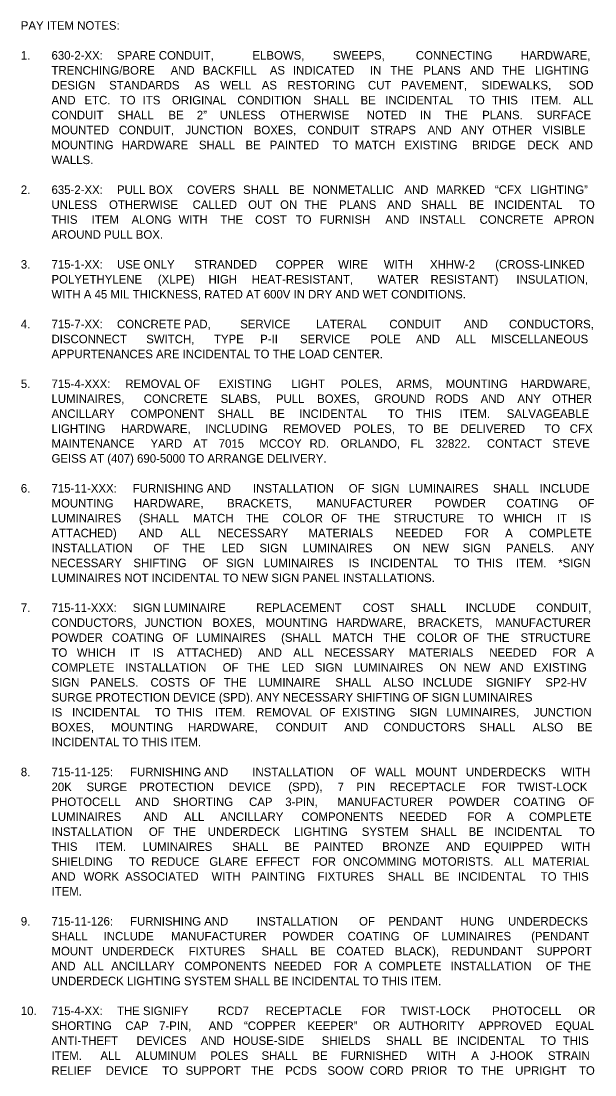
# Model space of a CAD drawing. Extents: x -55 to 2471539, y -90 to 3608906.
# Drawn here: x 27 to 498, y 2532 to 3397 of the extents above; entities that cross this region are included whole.
import ezdxf

# ---------------------------------------------------------------- set-up
doc = ezdxf.new("R2010")
doc.units = 0
doc.layers.add('XSCell', color=7, linetype='Continuous')

msp = doc.modelspace()

# ---------------------------------------------------------------- texts
at = {"layer": 'XSCell'}
for s, p in [('PAY ITEM NOTES:', (26.68, 3389.74)), ('630-2-XX:', (51.88, 3365.24)), (' SPARE CONDUIT, ', (103, 3365.24)), ('ELBOWS, ', (216.8, 3365.24)), ('SWEEPS, ', (282.82, 3365.24)), ('CONNECTING ', (350.92, 3365.24)), ('1.', (26.68, 3365.24)), ('HARDWARE, ', (437.06, 3365.24)), ('TRENCHING/BORE ', (51.88, 3352.99)), ('AND ', (149.66, 3352.99)), ('BACKFILL ', (176.11, 3352.99)), ('AS ', (231.06, 3352.99)), ('INDICATED ', (249.96, 3352.99)), ('IN ', (313.22, 3352.99)), ('THE ', (330.09, 3352.99)), ('PLANS ', (357.07, 3352.99)), ('AND ', (395.32, 3352.99)), ('THE ', (421.77, 3352.99)), ('LIGHTING ', (448.75, 3352.99)), ('DESIGN ', (51.88, 3340.74)), ('STANDARDS ', (99.2, 3340.74)), ('AS ', (169.29, 3340.74)), ('WELL ', (190.33, 3340.74)), ('AS ', (224.46, 3340.74)), ('RESTORING ', (245.49, 3340.74)), ('CUT ', (311.63, 3340.74)), ('PAVEMENT, ', (338.81, 3340.74)), ('SIDEWALKS, ', (404.84, 3340.74)), ('SOD ', (476.42, 3340.74)), ('AND ', (51.88, 3328.49)), ('ETC. ', (78.98, 3328.49)), ('TO ', (107.88, 3328.49)), ('ITS ', (126.69, 3328.49)), ('ORIGINAL ', (150.74, 3328.49)), ('CONDITION ', (204.43, 3328.49)), ('SHALL ', (266.79, 3328.49)), ('BE ', (305.52, 3328.49)), ('INCIDENTAL ', (325.8, 3328.49)), ('TO ', (394.52, 3328.49)), ('THIS ', (413.34, 3328.49)), ('ITEM. ', (445.46, 3328.49)), ('ALL ', (480.05, 3328.49)), ('CONDUIT ', (51.88, 3316.24)), ('SHALL ', (106.12, 3316.24)), ('BE ', (147.86, 3316.24)), ('2” ', (171.15, 3316.24)), ('UNLESS ', (190.04, 3316.24)), ('OTHERWISE ', (239.61, 3316.24)), ('NOTED ', (310.61, 3316.24)), ('IN ', (354.19, 3316.24)), ('THE ', (374.74, 3316.24)), ('PLANS. ', (405.39, 3316.24)), ('SURFACE ', (450.07, 3316.24)), ('MOUNTED ', (51.88, 3303.99)), ('CONDUIT, ', (107.18, 3303.99)), ('JUNCTION ', (161.77, 3303.99)), ('BOXES, ', (217.91, 3303.99)), ('CONDUIT ', (262.01, 3303.99)), ('STRAPS ', (313.55, 3303.99)), ('AND ', (360.6, 3303.99)), ('ANY ', (388, 3303.99)), ('OTHER ', (413.64, 3303.99)), ('VISIBLE ', (454.83, 3303.99)), ('MOUNTING ', (51.88, 3291.74)), ('HARDWARE ', (109.45, 3291.74)), ('SHALL ', (172.87, 3291.74)), ('BE ', (211.11, 3291.74)), ('PAINTED ', (230.91, 3291.74)), ('TO ', (282.44, 3291.74)), ('MATCH ', (300.77, 3291.74)), ('EXISTING ', (341.5, 3291.74)), ('BRIDGE ', (397.1, 3291.74)), ('DECK ', (442.4, 3291.74)), ('AND ', (476.52, 3291.74)), ('WALLS.', (51.88, 3279.49)), ('2.', (26.68, 3254.99)), ('635-2-XX:', (51.88, 3254.99)), (' PULL BOX ', (103, 3254.99)), ('COVERS ', (163.1, 3254.99)), ('SHALL ', (209.1, 3254.99)), ('BE ', (246.91, 3254.99)), ('NONMETALLIC ', (266.27, 3254.99)), ('AND ', (341.51, 3254.99)), ('MARKED ', (367.7, 3254.99)), ('“CFX ', (415.84, 3254.99)), ('LIGHTING” ', (444.82, 3254.99)), ('UNLESS ', (51.88, 3242.74)), ('OTHERWISE ', (99.08, 3242.74)), ('CALLED ', (167.72, 3242.74)), ('OUT ', (213.33, 3242.74)), ('ON ', (239.5, 3242.74)), ('THE ', (259.52, 3242.74)), ('PLANS ', (287.82, 3242.74)), ('AND ', (327.38, 3242.74)), ('SHALL ', (355.13, 3242.74)), ('BE ', (394.51, 3242.74)), ('INCIDENTAL ', (415.44, 3242.74)), ('TO ', (484.81, 3242.74)), ('THIS ', (51.88, 3230.49)), ('ITEM ', (84.87, 3230.49)), ('ALONG ', (117.57, 3230.49)), ('WITH ', (156.2, 3230.49)), ('THE ', (190.47, 3230.49)), ('COST ', (218.99, 3230.49)), ('TO ', (252.31, 3230.49)), ('FURNISH ', (272, 3230.49)), ('AND ', (325.85, 3230.49)), ('INSTALL ', (353.83, 3230.49)), ('CONCRETE ', (403.21, 3230.49)), ('APRON ', (464.1, 3230.49)), ('AROUND PULL BOX.', (51.88, 3218.24)), ('3.', (26.68, 3193.74)), ('715-1-XX:', (51.88, 3193.74)), (' USE ONLY ', (103, 3193.74)), ('STRANDED ', (169.1, 3193.74)), ('COPPER ', (235.88, 3193.74)), ('WIRE ', (287.14, 3193.74)), ('WITH ', (324.62, 3193.74)), ('XHHW-2 ', (362.53, 3193.74)), ('(CROSS-LINKED ', (416.09, 3193.74)), ('POLYETHYLENE ', (51.88, 3181.49)), ('(XLPE) ', (139.17, 3181.49)), ('HIGH ', (180.77, 3181.49)), ('HEAT-RESISTANT, ', (216.17, 3181.49)), ('WATER ', (319.51, 3181.49)), ('RESISTANT) ', (362.99, 3181.49)), ('INSULATION, ', (433.46, 3181.49)), ('WITH A 45 MIL THICKNESS, RATED AT 600V IN DRY AND WET CONDITIONS.', (51.88, 3169.24)), ('4.', (26.68, 3144.74)), ('715-7-XX:', (51.88, 3144.74)), (' CONCRETE PAD, ', (103, 3144.74)), ('SERVICE ', (206.77, 3144.74)), ('LATERAL ', (268.9, 3144.74)), ('CONDUIT ', (329.2, 3144.74)), ('AND ', (390.35, 3144.74)), ('CONDUCTORS, ', (427.37, 3144.74)), ('DISCONNECT ', (51.88, 3132.49)), ('SWITCH, ', (129.64, 3132.49)), ('TYPE ', (185.25, 3132.49)), ('P-II ', (223.15, 3132.49)), ('SERVICE ', (255.82, 3132.49)), ('POLE ', (313.56, 3132.49)), ('AND ', (351.06, 3132.49)), ('ALL ', (383.69, 3132.49)), ('MISCELLANEOUS ', (412.79, 3132.49)), ('APPURTENANCES ARE INCIDENTAL TO THE LOAD CENTER.', (51.88, 3120.24)), ('5.', (26.68, 3095.74)), ('715-4-XXX:', (51.88, 3095.74)), (' REMOVAL OF ', (109.83, 3095.74)), ('EXISTING ', (189.18, 3095.74)), ('LIGHT ', (248.74, 3095.74)), ('POLES, ', (289.22, 3095.74)), ('ARMS, ', (334.82, 3095.74)), ('MOUNTING ', (375.52, 3095.74)), ('HARDWARE, ', (437.06, 3095.74)), ('LUMINAIRES, ', (51.88, 3083.49)), ('CONCRETE ', (127.57, 3083.49)), ('SLABS, ', (190.68, 3083.49)), ('PULL ', (236.09, 3083.49)), ('BOXES, ', (269.91, 3083.49)), ('GROUND ', (316.81, 3083.49)), ('RODS ', (366.94, 3083.49)), ('AND ', (404.11, 3083.49)), ('ANY ', (434.3, 3083.49)), ('OTHER ', (462.73, 3083.49)), ('ANCILLARY ', (51.88, 3071.24)), ('COMPONENT ', (116.74, 3071.24)), ('SHALL ', (188.11, 3071.24)), ('INCIDENTAL ', (255.18, 3071.24)), ('TO ', (327.94, 3071.24)), ('THIS ', (350.78, 3071.24)), ('SALVAGEABLE ', (425.56, 3071.24)), ('BE ', (230.87, 3071.24)), ('ITEM. ', (386.93, 3071.24)), ('LIGHTING ', (51.88, 3058.99)), ('HARDWARE, ', (108.88, 3058.99)), ('INCLUDING ', (177.96, 3058.99)), ('REMOVED ', (242, 3058.99)), ('POLES, ', (299.96, 3058.99)), ('TO ', (344.21, 3058.99)), ('BE ', (365.15, 3058.99)), ('DELIVERED ', (387.56, 3058.99)), ('TO ', (456.32, 3058.99)), ('CFX ', (477.26, 3058.99)), ('MAINTENANCE ', (51.88, 3046.74)), ('YARD ', (133.12, 3046.74)), ('AT ', (168.17, 3046.74)), ('7015 ', (189.1, 3046.74)), ('MCCOY ', (222.38, 3046.74)), ('RD. ', (263.67, 3046.74)), ('ORLANDO, ', (289.13, 3046.74)), ('FL ', (346.54, 3046.74)), ('32822. ', (366.95, 3046.74)), ('CONTACT ', (409.27, 3046.74)), ('STEVE ', (463.01, 3046.74)), ('GEISS AT (407) 690-5000 TO ARRANGE DELIVERY.', (51.88, 3034.49)), ('6.', (26.68, 3009.99)), ('715-11-XXX:', (51.88, 3009.99)), (' FURNISHING AND ', (115.94, 3009.99)), ('INSTALLATION ', (217.19, 3009.99)), ('OF ', (295.86, 3009.99)), ('SIGN ', (314.55, 3009.99)), ('LUMINAIRES ', (345.11, 3009.99)), ('SHALL ', (414.2, 3009.99)), ('INCLUDE ', (452.46, 3009.99)), ('MOUNTING ', (51.88, 2997.74)), ('HARDWARE, ', (119.48, 2997.74)), ('BRACKETS, ', (195.97, 2997.74)), ('MANUFACTURER ', (269.31, 2997.74)), ('POWDER ', (366.37, 2997.74)), ('COATING ', (425.27, 2997.74)), ('OF ', (484.48, 2997.74)), ('LUMINAIRES ', (51.88, 2985.49)), ('(SHALL ', (123.68, 2985.49)), ('MATCH ', (168.01, 2985.49)), ('THE ', (211.48, 2985.49)), ('COLOR ', (241.38, 2985.49)), ('OF ', (281.43, 2985.49)), ('THE ', (302.84, 2985.49)), ('STRUCTURE ', (332.74, 2985.49)), ('TO ', (401.75, 2985.49)), ('WHICH ', (422.82, 2985.49)), ('IT ', (466.72, 2985.49)), ('IS ', (485.95, 2985.49)), ('ATTACHED) ', (51.88, 2973.24)), ('AND ', (123.47, 2973.24)), ('ALL ', (157.72, 2973.24)), ('NECESSARY ', (188.45, 2973.24)), ('MATERIALS ', (262.81, 2973.24)), ('NEEDED ', (334.12, 2973.24)), ('FOR ', (391.05, 2973.24)), ('A ', (424.22, 2973.24)), ('COMPLETE ', (443.85, 2973.24)), ('INSTALLATION ', (51.88, 2960.99)), ('OF ', (135.58, 2960.99)), ('THE ', (159.31, 2960.99)), ('LED ', (191.53, 2960.99)), ('SIGN ', (222.55, 2960.99)), ('LUMINAIRES ', (258.15, 2960.99)), ('ON ', (332.27, 2960.99)), ('NEW ', (356.22, 2960.99)), ('SIGN ', (389.3, 2960.99)), ('PANELS. ', (424.89, 2960.99)), ('ANY ', (478.27, 2960.99)), ('NECESSARY ', (51.88, 2948.74)), ('SHIFTING ', (119.12, 2948.74)), ('OF ', (175.87, 2948.74)), ('SIGN ', (195.05, 2948.74)), ('LUMINAIRES ', (226.1, 2948.74)), ('IS ', (295.69, 2948.74)), ('INCIDENTAL ', (313.39, 2948.74)), ('TO ', (382.15, 2948.74)), ('THIS ', (400.99, 2948.74)), ('ITEM. ', (433.14, 2948.74)), ('*SIGN ', (467.76, 2948.74)), ('LUMINAIRES NOT INCIDENTAL TO NEW SIGN PANEL INSTALLATIONS.', (51.88, 2936.49)), ('7.', (26.68, 2911.99)), ('715-11-XXX:', (51.88, 2911.99)), (' SIGN LUMINAIRE ', (115.94, 2911.99)), ('REPLACEMENT ', (219.87, 2911.99)), ('COST ', (307.32, 2911.99)), ('SHALL ', (346.46, 2911.99)), ('INCLUDE ', (391.87, 2911.99)), ('CONDUIT, ', (449.72, 2911.99)), ('CONDUCTORS, ', (51.88, 2899.74)), ('JUNCTION ', (128.38, 2899.74)), ('BOXES, ', (184.07, 2899.74)), ('MOUNTING ', (227.74, 2899.74)), ('HARDWARE, ', (285.65, 2899.74)), ('BRACKETS, ', (352.46, 2899.74)), ('MANUFACTURER ', (416.11, 2899.74)), ('POWDER ', (51.88, 2887.49)), ('COATING ', (101.4, 2887.49)), ('OF ', (151.24, 2887.49)), ('LUMINAIRES ', (170.57, 2887.49)), ('(SHALL ', (240.3, 2887.49)), ('MATCH ', (282.55, 2887.49)), ('THE ', (323.94, 2887.49)), ('COLOR ', (351.76, 2887.49)), ('OF ', (389.72, 2887.49)), ('THE ', (409.05, 2887.49)), ('STRUCTURE ', (436.87, 2887.49)), ('TO ', (51.88, 2875.24)), ('WHICH ', (72.65, 2875.24)), ('IT ', (116.27, 2875.24)), ('IS ', (135.21, 2875.24)), ('ATTACHED) ', (154.85, 2875.24)), ('AND ', (221.27, 2875.24)), ('ALL ', (250.34, 2875.24)), ('NECESSARY ', (275.89, 2875.24)), ('MATERIALS ', (345.07, 2875.24)), ('NEEDED ', (411.2, 2875.24)), ('FOR ', (462.95, 2875.24)), ('A ', (490.95, 2875.24)), ('COMPLETE ', (51.88, 2862.99)), ('INSTALLATION ', (112.45, 2862.99)), ('OF ', (192.38, 2862.99)), ('THE ', (212.33, 2862.99)), ('LED ', (240.77, 2862.99)), ('SIGN ', (268.01, 2862.99)), ('LUMINAIRES ', (299.83, 2862.99)), ('ON ', (370.17, 2862.99)), ('NEW ', (390.34, 2862.99)), ('AND ', (419.64, 2862.99)), ('EXISTING ', (447.54, 2862.99)), ('SIGN ', (51.88, 2850.74)), ('PANELS. ', (83.62, 2850.74)), ('COSTS ', (133.14, 2850.74)), ('OF ', (173.39, 2850.74)), ('THE ', (193.26, 2850.74)), ('LUMINAIRE ', (221.62, 2850.74)), ('SHALL ', (284.81, 2850.74)), ('ALSO ', (324.26, 2850.74)), ('INCLUDE ', (356.45, 2850.74)), ('SIGNIFY ', (408.34, 2850.74)), ('SP2-HV ', (457.26, 2850.74)), ('SURGE PROTECTION DEVICE (SPD). ANY NECESSARY SHIFTING OF SIGN LUMINAIRES ', (51.88, 2838.49)), ('IS ', (51.88, 2826.24)), ('INCIDENTAL ', (68.77, 2826.24)), ('TO ', (136.7, 2826.24)), ('THIS ', (154.73, 2826.24)), ('ITEM. ', (186.07, 2826.24)), ('REMOVAL ', (219.87, 2826.24)), ('OF ', (272.05, 2826.24)), ('EXISTING ', (290.42, 2826.24)), ('SIGN ', (345.72, 2826.24)), ('LUMINAIRES, ', (375.96, 2826.24)), ('JUNCTION ', (447.79, 2826.24)), ('BOXES, ', (51.88, 2813.99)), ('MOUNTING ', (100.75, 2813.99)), ('HARDWARE, ', (163.88, 2813.99)), ('CONDUIT ', (235.9, 2813.99)), ('AND ', (292.19, 2813.99)), ('CONDUCTORS ', (324.36, 2813.99)), ('SHALL ', (403.02, 2813.99)), ('ALSO ', (446.81, 2813.99)), ('BE ', (483.35, 2813.99)), ('INCIDENTAL TO THIS ITEM.', (51.88, 2801.74)), ('8.', (26.68, 2777.24)), ('715-11-125:', (51.88, 2777.24)), (' FURNISHING AND ', (113.78, 2777.24)), ('INSTALLATION ', (216.71, 2777.24)), ('OF ', (297.06, 2777.24)), ('WALL ', (317.43, 2777.24)), ('MOUNT ', (350.59, 2777.24)), ('UNDERDECKS ', (391.99, 2777.24)), ('WITH ', (470.23, 2777.24)), ('20K ', (51.88, 2764.99)), ('SURGE ', (80.64, 2764.99)), ('PROTECTION ', (123.89, 2764.99)), ('DEVICE ', (197.33, 2764.99)), ('(SPD), ', (246.25, 2764.99)), ('7 ', (286.69, 2764.99)), ('PIN ', (302.02, 2764.99)), ('RECEPTACLE ', (329.39, 2764.99)), ('FOR ', (405.04, 2764.99)), ('TWIST-LOCK ', (434.05, 2764.99)), ('PHOTOCELL ', (51.88, 2752.74)), ('AND ', (120.6, 2752.74)), ('SHORTING ', (151.52, 2752.74)), ('CAP ', (214.05, 2752.74)), ('3-PIN, ', (243.77, 2752.74)), ('MANUFACTURER ', (286.49, 2752.74)), ('POWDER ', (377.83, 2752.74)), ('COATING ', (431, 2752.74)), ('OF ', (484.48, 2752.74)), ('LUMINAIRES ', (51.88, 2740.49)), ('AND ', (127.45, 2740.49)), ('ALL ', (160.58, 2740.49)), ('ANCILLARY ', (190.18, 2740.49)), ('COMPONENTS ', (257.03, 2740.49)), ('NEEDED ', (337.48, 2740.49)), ('FOR ', (393.29, 2740.49)), ('A ', (425.34, 2740.49)), ('COMPLETE ', (443.85, 2740.49)), ('INSTALLATION ', (51.88, 2728.24)), ('OF ', (131.79, 2728.24)), ('THE ', (151.73, 2728.24)), ('UNDERDECK ', (180.16, 2728.24)), ('LIGHTING ', (250.89, 2728.24)), ('SYSTEM ', (306.55, 2728.24)), ('SHALL ', (354.73, 2728.24)), ('BE ', (394.24, 2728.24)), ('INCIDENTAL ', (415.3, 2728.24)), ('TO ', (484.81, 2728.24)), ('THIS ', (51.88, 2715.99)), ('ITEM. ', (88.03, 2715.99)), ('LUMINAIRES ', (126.65, 2715.99)), ('SHALL ', (200.23, 2715.99)), ('BE ', (242.98, 2715.99)), ('PAINTED ', (267.29, 2715.99)), ('BRONZE ', (323.33, 2715.99)), ('AND ', (375.7, 2715.99)), ('EQUIPPED ', (406.84, 2715.99)), ('WITH ', (470.23, 2715.99)), ('SHIELDING ', (51.88, 2703.74)), ('TO ', (115.39, 2703.74)), ('REDUCE ', (133.72, 2703.74)), ('GLARE ', (181.41, 2703.74)), ('EFFECT ', (219.38, 2703.74)), ('FOR ', (265.61, 2703.74)), ('ONCOMMING ', (291.16, 2703.74)), ('MOTORISTS. ', (356.32, 2703.74)), ('ALL ', (423.44, 2703.74)), ('MATERIAL ', (446.54, 2703.74)), ('AND ', (51.88, 2691.49)), ('WORK ', (78.23, 2691.49)), ('ASSOCIATED ', (112.3, 2691.49)), ('WITH ', (183.26, 2691.49)), ('PAINTING ', (215.9, 2691.49)), ('FIXTURES ', (270.22, 2691.49)), ('SHALL ', (327.97, 2691.49)), ('BE ', (365.95, 2691.49)), ('INCIDENTAL ', (385.47, 2691.49)), ('TO ', (453.45, 2691.49)), ('THIS ', (471.51, 2691.49)), ('ITEM. ', (51.88, 2679.24)), ('9.', (26.68, 2654.74)), ('715-11-126:', (51.88, 2654.74)), (' FURNISHING AND ', (113.78, 2654.74)), ('INSTALLATION ', (220.34, 2654.74)), ('OF ', (304.31, 2654.74)), ('PENDANT ', (328.31, 2654.74)), ('HUNG ', (387.57, 2654.74)), ('UNDERDECKS ', (426.6, 2654.74)), ('SHALL ', (51.88, 2642.49)), ('INCLUDE ', (94.68, 2642.49)), ('MANUFACTURER ', (149.93, 2642.49)), ('POWDER ', (241.52, 2642.49)), ('COATING ', (294.95, 2642.49)), ('OF ', (348.69, 2642.49)), ('LUMINAIRES ', (371.93, 2642.49)), ('(PENDANT ', (445.55, 2642.49)), ('BLACK), ', (333.58, 2630.24)), ('MOUNT ', (51.88, 2630.24)), ('UNDERDECK ', (93.3, 2630.24)), ('FIXTURES ', (164.49, 2630.24)), ('SHALL ', (224.24, 2630.24)), ('BE ', (264.21, 2630.24)), ('COATED ', (285.73, 2630.24)), ('REDUNDANT ', (380.06, 2630.24)), ('SUPPORT ', (450.12, 2630.24)), ('AND ', (51.88, 2617.99)), ('ALL ', (78.16, 2617.99)), ('ANCILLARY ', (100.92, 2617.99)), ('COMPONENTS ', (160.93, 2617.99)), ('NEEDED ', (234.54, 2617.99)), ('FOR ', (283.5, 2617.99)), ('A ', (308.71, 2617.99)), ('COMPLETE ', (320.38, 2617.99)), ('INSTALLATION ', (379.34, 2617.99)), ('OF ', (457.65, 2617.99)), ('THE ', (475.98, 2617.99)), ('UNDERDECK LIGHTING SYSTEM SHALL BE INCIDENTAL TO THIS ITEM.', (51.88, 2605.74)), ('10.', (26.68, 2581.24)), ('715-4-XX:', (51.88, 2581.24)), (' THE SIGNIFY ', (103, 2581.24)), ('RCD7 ', (188.43, 2581.24)), ('RECEPTACLE ', (227.75, 2581.24)), ('FOR ', (306.27, 2581.24)), ('TWIST-LOCK ', (338.14, 2581.24)), ('PHOTOCELL ', (413.56, 2581.24)), ('OR ', (484.31, 2581.24)), ('SHORTING ', (51.88, 2568.99)), ('CAP ', (112.43, 2568.99)), ('7-PIN, ', (140.18, 2568.99)), ('AND ', (180.93, 2568.99)), ('“COPPER ', (209.87, 2568.99)), ('KEEPER” ', (261.99, 2568.99)), ('OR ', (315.72, 2568.99)), ('AUTHORITY ', (336.88, 2568.99)), ('APPROVED ', (402.43, 2568.99)), ('EQUAL ', (465.38, 2568.99)), ('ANTI-THEFT ', (51.88, 2556.74)), ('DEVICES ', (121.66, 2556.74)), ('AND ', (174.3, 2556.74)), ('HOUSE-SIDE ', (201.03, 2556.74)), ('SHIELDS ', (273.67, 2556.74)), ('SHALL ', (326.48, 2556.74)), ('BE ', (364.83, 2556.74)), ('INCIDENTAL ', (384.73, 2556.74)), ('TO ', (453.07, 2556.74)), ('THIS ', (471.51, 2556.74)), ('ITEM. ', (51.88, 2544.49)), (' ALL ', (89.44, 2544.49)), ('ALUMINUM ', (120.9, 2544.49)), ('POLES ', (182.23, 2544.49)), ('SHALL ', (224.27, 2544.49)), ('BE ', (265.97, 2544.49)), ('FURNISHED ', (289.22, 2544.49)), ('WITH ', (360, 2544.49)), ('A ', (396.37, 2544.49)), ('J-HOOK ', (411.83, 2544.49)), ('STRAIN ', (459.35, 2544.49)), ('RELIEF ', (51.88, 2532.24)), ('DEVICE ', (96.33, 2532.24)), ('TO ', (142.72, 2532.24)), ('SUPPORT ', (161.97, 2532.24)), ('THE ', (215.62, 2532.24)), ('PCDS ', (243.71, 2532.24)), ('SOOW ', (278.41, 2532.24)), ('CORD ', (313.1, 2532.24)), ('PRIOR ', (347.1, 2532.24)), ('TO ', (385.13, 2532.24)), ('THE ', (404.38, 2532.24)), ('UPRIGHT ', (432.47, 2532.24)), ('TO ', (484.81, 2532.24))]:
    msp.add_text(s, height=7, dxfattribs=at).set_placement(p)

doc.saveas('drawing.dxf')
